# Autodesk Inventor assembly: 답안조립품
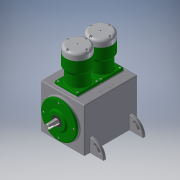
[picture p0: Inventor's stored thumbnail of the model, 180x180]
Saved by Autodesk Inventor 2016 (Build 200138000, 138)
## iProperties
Created: 2017-03
Part Number: 답안조립품
Material: 일반
Document SubType Name: Assembly
Designer: USER
Mass: 8958.37 g
Surface Area: 6668.35 cm^2
Volume: 2429.28 cm^3
Density: 3.68767 g/cm^3
Author: USER
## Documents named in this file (18)
- C:\Users\USER\Desktop\370307V1026\답안조립품.iam
- C:\Users\USER\Desktop\370307V1026\본체.ipt
- C:\Users\USER\Desktop\370307V1026\베어링 20 x 47 x 14.ipt
- C:\Users\USER\Desktop\370307V1026\크랭크축.ipt
- C:\Users\USER\Desktop\370307V1026\앞커버.ipt
- C:\Users\USER\Desktop\370307V1026\오일 실 20 35 8.ipt
- C:\Users\USER\Desktop\370307V1026\볼트 M4 x 8.ipt
- C:\Users\USER\Desktop\370307V1026\커넥팅로드.ipt
- C:\Users\USER\Desktop\370307V1026\커넥팅로드 엔드.ipt
- C:\Users\USER\Desktop\370307V1026\육각머리볼트 M4 x 16.ipt
- C:\Users\USER\Desktop\370307V1026\너트 M4.ipt
- C:\Users\USER\Desktop\370307V1026\피스톤핀.ipt
- C:\Users\USER\Desktop\370307V1026\피스톤.ipt
- C:\Users\USER\Desktop\370307V1026\실린더.ipt
- C:\Users\USER\Desktop\370307V1026\실린더헤드.ipt
- C:\Users\USER\Desktop\370307V1026\볼트 M5 x 20.ipt
- C:\Users\USER\Desktop\370307V1026\가변스프링1.ipt
- C:\Users\USER\Desktop\370307V1026\가변스프링2.ipt
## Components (34 placed, 8 different names)
1. KS B 1002 A+B - 미터 A + B M4 x 16:1
2. KS B 1012 스타일 1 - 미터 A M4:1
3. KS B 1002 A+B - 미터 A + B M4 x 16:2
4. KS B 1012 스타일 1 - 미터 A M4:2
5. KS B 1002 A+B - 미터 A + B M4 x 16:3
6. KS B 1002 A+B - 미터 A + B M4 x 16:4
7. KS B 1012 스타일 1 - 미터 A M4:3
8. KS B 1012 스타일 1 - 미터 A M4:4
9. 피스톤핀:1
10. 피스톤핀:2
11. 피스톤:1
12. 피스톤:2
13. 가변스프링1:1
14. 가변스프링2:1
15. ISO 4762 M4 x 8:1
16. ISO 4762 M4 x 8:2
17. ISO 4762 M4 x 8:3
18. ISO 4762 M4 x 8:4
19. ISO 4762 M4 x 8:5
20. ISO 4762 M4 x 8:6
21. ISO 4762 M4 x 8:7
22. ISO 4762 M4 x 8:8
23. ISO 4762 M4 x 8:9
24. ISO 4762 M4 x 8:10
25. ISO 4762 M4 x 8:11
26. ISO 4762 M4 x 8:12
27. ISO 4762 M5 x 20:1
28. ISO 4762 M5 x 20:3
29. ISO 4762 M5 x 20:4
30. ISO 4762 M5 x 20:5
31. ISO 4762 M5 x 20:2
32. ISO 4762 M5 x 20:6
33. ISO 4762 M5 x 20:7
34. ISO 4762 M5 x 20:8
